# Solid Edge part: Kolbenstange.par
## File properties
Dokumentum tartalom típus: 0
Last saved by: bmolnar
Revision: 78
Sűrűség: 0,000 kg/m^3
Pontosság: 0,990
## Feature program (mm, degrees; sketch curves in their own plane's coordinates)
base feature "unnamed BaseFeature 1"
sketch for "unnamed Protrusion 1" plane through (-0.0012, 0, -21.25) normal (0, 0, -1) x-axis (0, 1, 0)
  circle centre (0, 0.0012) radius 31.5
extrude "unnamed Protrusion 1" add finite 3.5 along +normal
sketch for "Furat_1" plane through (0, 0, 18.5163) normal (0, 0, 1) x-axis (0, 1, 0)
  hole centre (0, 0) bore radius 3.3235
hole "Furat_1" nominal diameter 8 finite  VBottomAngle = 118 deg; ThreadDepth = 14.27 mm
chamfer "Letörés_1" setback 0.7  SetBackValue2 = 45 deg
sketch for "Kihúzás_3" plane through (-0.0012, 0, -21.25) normal (0, 0, -1) x-axis (0, 1, 0)
extrude "Kihúzás_3" add finite 11 along -normal
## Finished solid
Body 1: solid body, 17 faces, 23 edges, 11 vertices.
  Faces by surface: plane 8, cylinder 5, cone 3, torus 1
  Edges by curve: circle 13, line 6, curve on surface 2, ellipse 2
Bounding box of the edges (mm; curved faces can reach further): 63.000 x 63.000 x 46.000, from (-31.5, -31.5, -24.75) to (31.5, 31.5, 21.25).
Cylindrical faces by radius (mm): R3.3235 x2, R4.125 x1, R8 x1, R31.5 x1
Conical faces (half-angle, radius in mm at the cone's reference point): 45 deg R4.0235 x1, 45 deg R4.225 x1, 59 deg R3.3235 x1
Toroidal faces (ring radius, tube radius in mm): R6.2 r1.8 x1
Planar faces by outward normal: +x 1, +z 3, -x 1, -z 1, oblique 2
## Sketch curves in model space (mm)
circle centre (0, 0, -21.25) radius 31.5
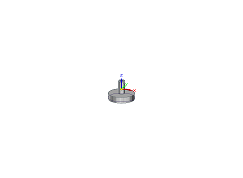
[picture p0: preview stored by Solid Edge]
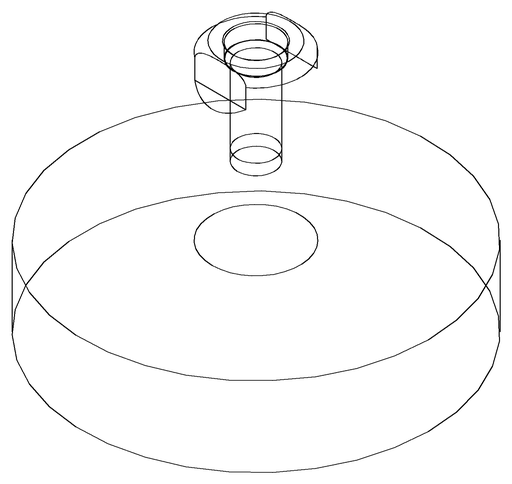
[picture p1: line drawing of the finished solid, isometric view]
